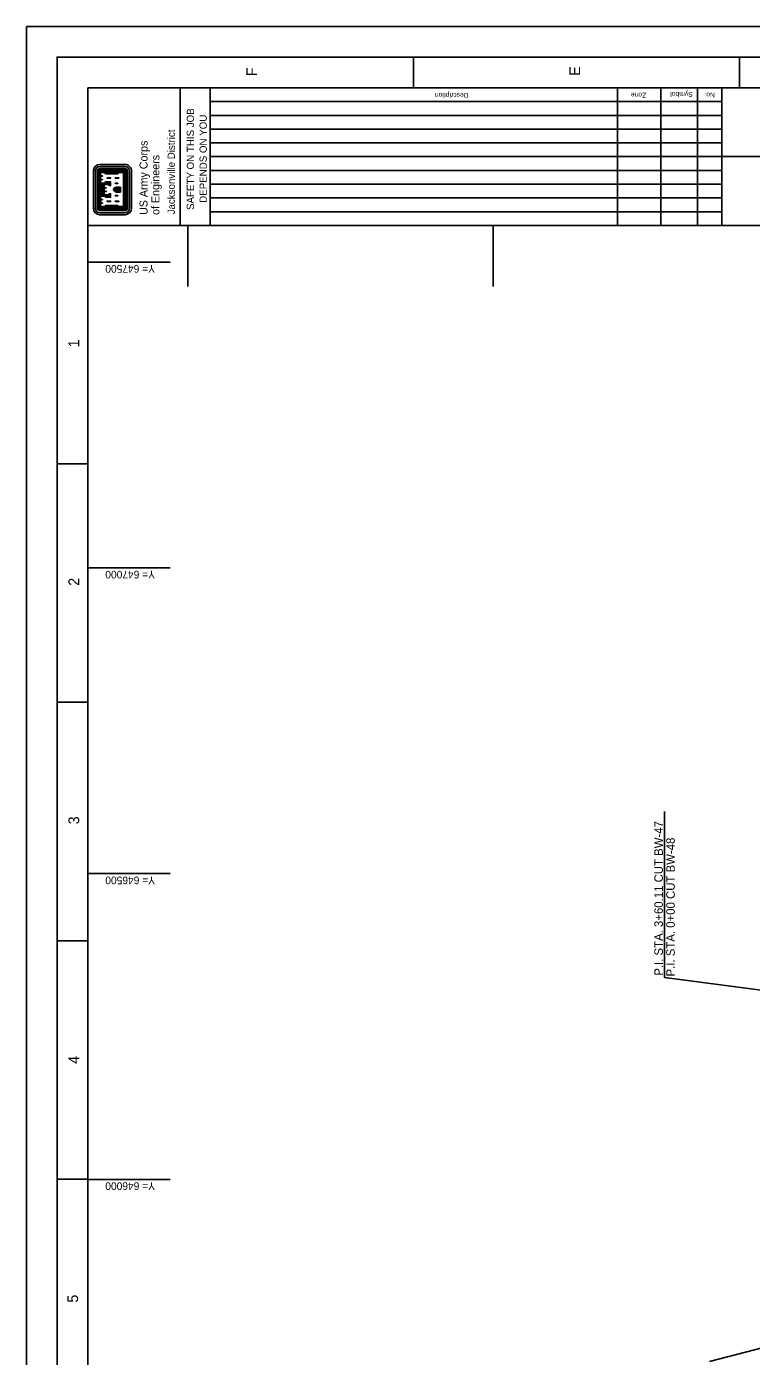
# Model space of a CAD drawing. Extents: x 943236 to 946636, y 643485 to 647885.
# Drawn here: x 943236 to 944423, y 645710 to 647885 of the extents above; entities that cross this region are included whole.
import ezdxf

# ---------------------------------------------------------------- set-up
doc = ezdxf.new("R2010")
doc.units = 0
for name, color, linetype in [('G-ANNO-NPLT', 7, 'Continuous'), ('G-ANNO-TEXT-LOGO', 7, 'Continuous'), ('G-ANNO-TEXT-TTLB', 7, 'Continuous'), ('G-ANNO-TTLB', 7, 'Continuous'), ('V-ALGN-TEXT', 7, 'Continuous'), ('V-TOPO-COOR-STAT', 7, 'Continuous')]:
    doc.layers.add(name, color=color, linetype=linetype)

msp = doc.modelspace()

# ---------------------------------------------------------------- linework, layer by layer
at = {"layer": 'G-ANNO-NPLT'}
msp.add_lwpolyline([(943236.1, 643485.2), (943236.1, 647885.2), (946636.1, 647885.2), (946636.1, 643485.2)], close=True, dxfattribs=at)
msp.add_lwpolyline([(943286.1, 647885.2), (943236.1, 647885.2), (943236.1, 647835.2)], dxfattribs=at)
at = {"layer": 'G-ANNO-TEXT-LOGO'}
for p, q in [((943345.5, 647649), (943345.5, 647588.2)), ((943348.7, 647588.2), (943348.7, 647649)), ((943352.1, 647649), (943352.1, 647588.2)), ((943353, 647649), (943353, 647588.2)), ((943353.9, 647649), (943353.9, 647588.2)), ((943354.7, 647649), (943354.7, 647588.2)), ((943355.6, 647649), (943355.6, 647588.2)), ((943397.2, 647659.7), (943356.2, 647659.7)), ((943356.2, 647656.4), (943397.2, 647656.4)), ((943356.2, 647653), (943397.2, 647653)), ((943356.2, 647652.1), (943397.2, 647652.1)), ((943356.2, 647651.2), (943397.2, 647651.2)), ((943356.2, 647650.4), (943397.2, 647650.4)), ((943356.2, 647649.5), (943397.2, 647649.5)), ((943356.2, 647648.6), (943396.9, 647648.6)), ((943356.2, 647647.8), (943396, 647647.8)), ((943365, 647647.1), (943385.8, 647647.1)), ((943365.8, 647646.2), (943384.9, 647646.2)), ((943396, 647647.8), (943396, 647589.4)), ((943396.9, 647648.6), (943396.9, 647588.6)), ((943397.8, 647649), (943397.8, 647588.2)), ((943398.6, 647649), (943398.6, 647588.2)), ((943399.5, 647649), (943399.5, 647588.2)), ((943400.4, 647649), (943400.4, 647588.2)), ((943401.2, 647649), (943401.2, 647588.2)), ((943404.7, 647649), (943404.7, 647588.2)), ((943408, 647588.2), (943408, 647649)), ((943356.4, 647609.3), (943356.4, 647627.9)), ((943357.3, 647609.3), (943357.3, 647627.9)), ((943358.1, 647609.3), (943358.1, 647627.9)), ((943359, 647609.3), (943359, 647627.9)), ((943359.9, 647609.3), (943359.9, 647627.9)), ((943360.7, 647609.3), (943360.7, 647627.9)), ((943361.6, 647609.3), (943361.6, 647627.9)), ((943390.1, 647622.6), (943383.4, 647622.6)), ((943390.1, 647621.8), (943383.4, 647621.8)), ((943390.1, 647620.9), (943383.4, 647620.9)), ((943390.1, 647620), (943383.4, 647620)), ((943390.1, 647619.2), (943383.4, 647619.2)), ((943390.1, 647618), (943383.4, 647618)), ((943390.1, 647617.2), (943383.4, 647617.2)), ((943390.1, 647616.3), (943383.4, 647616.3)), ((943390.1, 647615.4), (943383.4, 647615.4)), ((943390.1, 647614.6), (943383.4, 647614.6)), ((943390.1, 647614.6), (943390.1, 647622.6)), ((943356.2, 647589.4), (943396, 647589.4)), ((943356.2, 647588.6), (943396.9, 647588.6)), ((943356.2, 647587.7), (943397.2, 647587.7)), ((943356.2, 647586.8), (943397.2, 647586.8)), ((943356.2, 647585.9), (943397.2, 647585.9)), ((943356.2, 647585.1), (943397.2, 647585.1)), ((943356.2, 647584.2), (943397.2, 647584.2)), ((943397.2, 647580.7), (943356.2, 647580.7)), ((943364.9, 647590.1), (943385.9, 647590.1)), ((943365.8, 647591), (943384.9, 647591)), ((943356.2, 647577.5), (943397.2, 647577.5))]:
    msp.add_line(p, q, dxfattribs=at)
for points in [[(943356.2, 647590.1), (943364.1, 647590.1), (943365.8, 647591.8), (943384.9, 647591.8), (943386.7, 647590.1), (943395.4, 647590.1), (943395.4, 647647.1), (943386.7, 647647.1), (943384.9, 647645.3), (943365.8, 647645.3), (943364.1, 647647.1), (943356.2, 647647.1), (943356.2, 647639.6), (943356.2, 647633.8), (943356.2, 647628.4), (943364.1, 647628.4), (943365.8, 647630.3), (943372.8, 647630.3), (943372.8, 647626.1), (943372.1, 647626.1), (943370.3, 647627.9), (943362.5, 647627.9), (943362.5, 647620.4), (943362.5, 647614.6), (943362.5, 647609.3), (943370.3, 647609.3), (943372.1, 647611.1), (943372.8, 647611.1), (943372.8, 647606.9), (943365.8, 647606.9), (943364.1, 647608.7), (943356.2, 647608.7), (943356.2, 647601.2), (943356.2, 647595.4), (943356.2, 647590.1)], [(943357.1, 647590.9), (943363.7, 647590.9), (943365.5, 647592.7), (943385.3, 647592.7), (943387.1, 647590.9), (943394.5, 647590.9), (943394.5, 647646.3), (943387.1, 647646.3), (943385.3, 647644.4), (943365.5, 647644.4), (943363.7, 647646.3), (943357.1, 647646.3), (943357.1, 647640.9), (943360.2, 647640.9), (943360.2, 647640.4), (943357.1, 647640.4), (943357.1, 647635.1), (943360.2, 647635.1), (943360.2, 647634.7), (943357.1, 647634.7), (943357.1, 647629.3), (943363.7, 647629.3), (943365.5, 647631.1), (943373.6, 647631.1), (943373.6, 647625.3), (943371.7, 647625.3), (943369.9, 647627.1), (943363.3, 647627.1), (943363.3, 647621.7), (943366.4, 647621.7), (943366.4, 647621.3), (943363.3, 647621.3), (943363.3, 647615.9), (943366.4, 647615.9), (943366.4, 647615.4), (943363.3, 647615.4), (943363.3, 647610.1), (943369.9, 647610.1), (943371.7, 647611.9), (943373.6, 647611.9), (943373.6, 647606.1), (943365.5, 647606.1), (943363.7, 647607.9), (943357.1, 647607.9), (943357.1, 647602.6), (943360.2, 647602.6), (943360.2, 647602.1), (943357.1, 647602.1), (943357.1, 647596.7), (943360.2, 647596.7), (943360.2, 647596.3), (943357.1, 647596.3), (943357.1, 647590.9)], [(943365.7, 647628.9), (943366.2, 647629.4), (943371.9, 647629.4), (943371.9, 647627.6), (943370.6, 647628.8), (943365.6, 647628.8)], [(943367.8, 647638), (943373.6, 647638), (943373.6, 647637.5), (943367.8, 647637.5), (943367.8, 647638)], [(943381.1, 647638), (943387, 647638), (943387, 647637.5), (943381.1, 647637.5), (943381.1, 647638)], [(943381.1, 647628.9), (943385.2, 647628.9), (943385.2, 647628.4), (943381.1, 647628.4), (943381.1, 647628.9)], [(943365.7, 647608.3), (943366.2, 647607.8), (943371.9, 647607.8), (943371.9, 647609.7), (943370.6, 647608.4), (943365.6, 647608.4)], [(943381.1, 647608.3), (943385.2, 647608.3), (943385.2, 647608.8), (943381.1, 647608.8), (943381.1, 647608.3)], [(943367.8, 647599.1), (943373.6, 647599.1), (943373.6, 647599.7), (943367.8, 647599.7), (943367.8, 647599.1)], [(943381.1, 647599.1), (943387, 647599.1), (943387, 647599.7), (943381.1, 647599.7), (943381.1, 647599.1)]]:
    msp.add_lwpolyline(points, dxfattribs=at)
for centre, major_axis, start_param, end_param in [((943356.1, 647649), (0, 10.7), 6.283169, 7.853965), ((943356.1, 647649), (0, 7.49), 6.28317, 7.853966), ((943356.1, 647649), (0, 4.02), 6.283169, 7.853965), ((943356.1, 647649), (0, 3.15), 6.283169, 7.853965), ((943356.1, 647649), (0, 2.28), 6.283169, 7.853965), ((943356.1, 647649), (0, 1.41), 6.283169, 7.853965), ((943356.1, 647649), (0, 0.546), 6.283169, 7.853965), ((943397.2, 647649), (0, 10.7), 4.712373, 6.28317), ((943397.2, 647649), (0, -7.49), 1.570781, 3.141577), ((943397.2, 647649), (0, 4.02), 4.712373, 6.28317), ((943397.2, 647649), (0, 3.15), 4.712373, 6.28317), ((943397.2, 647649), (0, 2.28), 4.712373, 6.28317), ((943397.2, 647649), (0, 1.41), 4.712373, 6.28317), ((943397.2, 647649), (0, 0.546), 4.712373, 6.28317), ((943383.8, 647617.1), (0, 5.55), 0.068795, 1.29842), ((943383.8, 647620.1), (0, -5.55), 4.985832, 6.214359), ((943383.8, 647617.1), (0, 4.69), 0.068795, 1.335689), ((943383.8, 647620.1), (0, -4.69), 4.947465, 6.21436), ((943383.8, 647617.1), (0, 3.82), 0.068795, 1.335689), ((943383.8, 647620.1), (0, -3.82), 4.947465, 6.21436), ((943383.8, 647617.1), (0, 2.95), 0.068794, 1.335689), ((943383.8, 647620.1), (0, -2.95), 4.947465, 6.21436), ((943383.8, 647620.1), (0, -2.08), 4.947465, 6.214359), ((943383.8, 647617.1), (0, 2.08), 0.068794, 1.335689), ((943356.1, 647588.3), (0, 10.7), 1.57078, 3.141576), ((943356.1, 647588.3), (0, 7.49), 1.57078, 3.141576), ((943356.1, 647588.3), (0, 4.02), 1.57078, 3.141576), ((943356.1, 647588.3), (0, 3.15), 1.57078, 3.141576), ((943356.1, 647588.3), (0, 2.28), 1.57078, 3.141576), ((943356.1, 647588.3), (0, 1.41), 1.57078, 3.141576), ((943356.1, 647588.3), (0, 0.546), 1.57078, 3.141576), ((943397.2, 647588.3), (0, -4.02), 6.28317, 7.853966), ((943397.2, 647588.3), (0, -3.15), 6.28317, 7.853966), ((943397.2, 647588.3), (0, -2.28), 6.28317, 7.853966), ((943397.2, 647588.3), (0, -1.41), 6.28317, 7.853966), ((943397.2, 647588.3), (0, -0.546), 6.28317, 7.853966), ((943397.2, 647588.3), (0, -10.7), 6.28317, 7.853966), ((943397.2, 647588.3), (0, -7.49), 6.28317, 7.853966)]:
    msp.add_ellipse(centre, major_axis=major_axis, ratio=0.99964, start_param=start_param, end_param=end_param, dxfattribs=at)
at = {"layer": 'G-ANNO-TTLB'}
for p, q in [((943869.6, 647835.2), (943869.6, 647785.2)), ((944402.9, 647835.2), (944402.9, 647785.2)), ((943487.3, 647560.2), (943487.3, 647785.2)), ((943536.4, 647559.6), (943536.4, 647784.6)), ((944203.3, 647560.2), (944203.3, 647785.2)), ((944274.5, 647560.2), (944274.5, 647785.2)), ((944334.5, 647560.2), (944334.5, 647785.2)), ((944374.3, 647560.2), (944374.3, 647785.2)), ((943536.4, 647762.5), (944374.3, 647762.5)), ((943536.4, 647740), (944374.3, 647740)), ((943536.4, 647717.5), (944374.3, 647717.5)), ((943536.4, 647695), (944374.3, 647695)), ((943536.4, 647672.5), (944374.3, 647672.5)), ((945233.9, 647672), (944374.3, 647672.7)), ((944374.3, 647672.7), (944409.8, 647672.6)), ((943536.4, 647650), (944374.3, 647650)), ((943536.4, 647627.5), (944374.3, 647627.5)), ((943536.4, 647605), (944374.3, 647605)), ((943536.4, 647582.5), (944374.3, 647582.5)), ((943336.1, 647560.1), (946536.1, 647560.1)), ((943286.1, 647170.2), (943336.1, 647170.2)), ((943286.1, 646780.2), (943336.1, 646780.2)), ((943286.1, 646390.2), (943336.1, 646390.2)), ((943286.1, 646000.2), (943336.1, 646000.2))]:
    msp.add_line(p, q, dxfattribs=at)
for points in [[(946586.1, 643535.2), (946586.1, 647835.2), (943286.1, 647835.2), (943286.1, 643535.2)], [(943336.1, 647785.2), (943336.1, 643660.2), (946536.1, 643660.2), (946536.1, 647785.2)]]:
    msp.add_lwpolyline(points, close=True, dxfattribs=at)
at = {"layer": 'V-ALGN-TEXT'}
for p, q in [((944280.4, 646330.2), (944280.4, 646601.4)), ((944820.9, 646259.4), (944280.4, 646330.2)), ((944354.1, 645702.4), (944761.7, 645807.3))]:
    msp.add_line(p, q, dxfattribs=at)
at = {"layer": 'V-TOPO-COOR-STAT'}
for p, q in [((943500, 647460.1), (943500, 647560.1)), ((944000, 647460.1), (944000, 647560.1)), ((943471.1, 647500), (943336.1, 647500)), ((943471.1, 647000), (943336.1, 647000)), ((943471.1, 646500), (943336.1, 646500)), ((943471.1, 646000), (943336.1, 646000))]:
    msp.add_line(p, q, dxfattribs=at)

# ---------------------------------------------------------------- texts
at = {"layer": 'G-ANNO-TEXT-TTLB'}
for s, height, rotation, p in [('Description', 8, 180, (943959.6, 647776.8)), ('Zone', 8, 180, (944250.3, 647777.1)), ('Symbol', 8, 180, (944326.6, 647778.3)), ('No.', 8, 180, (944362.8, 647777.3)), ('SAFETY ON THIS JOB', 11.9, 90, (943510.2, 647585.3)), ('DEPENDS ON YOU', 11.9, 90, (943531.1, 647597)), ('Jacksonville District', 11.9, 90, (943478.8, 647578.1)), ('US Army Corps', 13.086, 90, (943434.1, 647577.1)), ('of Engineers', 13.086, 90, (943453.5, 647577.1))]:
    msp.add_text(s, height=height, rotation=rotation, dxfattribs=at).set_placement(p)
at = {"layer": 'G-ANNO-TTLB'}
for s, p in [('E', (944142.2, 647804.7)), ('F', (943613.4, 647804)), ('1', (943322.2, 647360.6)), ('2', (943322.2, 646970.6)), ('3', (943322.2, 646580.6)), ('4', (943322.2, 646188.9)), ('5', (943320.4, 645798.4))]:
    msp.add_text(s, height=17.5, rotation=90, dxfattribs=at).set_placement(p)
at = {"layer": 'V-ALGN-TEXT'}
for s, p in [('P.I. STA. 3+60.11 CUT BW-47', (944277.6, 646333)), ('P.I. STA. 0+00 CUT BW-48', (944297.1, 646331.8))]:
    msp.add_text(s, height=13.92, rotation=90, dxfattribs=at).set_placement(p)
at = {"layer": 'V-TOPO-COOR-STAT'}
for s, p in [('Y= 647500', (943446.3, 647495.2)), ('Y= 647000', (943446.3, 646995.2)), ('Y= 646500', (943446.3, 646495.2)), ('Y= 646000', (943446.3, 645995.2))]:
    msp.add_text(s, height=12.5, rotation=180, dxfattribs=at).set_placement(p)

doc.saveas('drawing.dxf')
